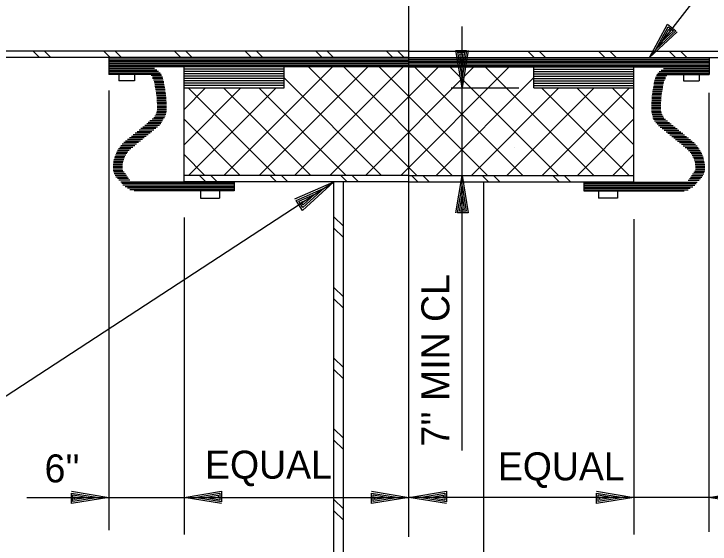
# Model space of a CAD drawing. Extents: x 22339.2 to 22413.4, y 22369.6 to 22418.8.
# Drawn here: x 22380.131 to 22384.774, y 22384.55 to 22388.086 of the extents above; entities that cross this region are included whole.
import ezdxf

# ---------------------------------------------------------------- set-up
doc = ezdxf.new("R2010")
doc.units = 0
for name, color, linetype in [('Level 1', 7, 'Continuous'), ('Level 10', 7, 'Continuous'), ('Level 2', 7, 'Continuous'), ('Level 4', 7, 'Continuous'), ('Level 8', 7, 'Continuous')]:
    doc.layers.add(name, color=color, linetype=linetype)

msp = doc.modelspace()

# ---------------------------------------------------------------- linework, layer by layer
at = {"layer": 'Level 1'}
for p, q in [((22382.7659, 22384.5979), (22382.7659, 22394.0328)), ((22383.1197, 22387.5922), (22383.1197, 22388.0015)), ((22381.2659, 22386.9672), (22381.2659, 22387.7328)), ((22381.9326, 22387.7172), (22381.2659, 22387.7172)), ((22383.5993, 22387.7172), (22384.2659, 22387.7172)), ((22384.2659, 22386.9672), (22384.2659, 22387.7328)), ((22380.8307, 22387.6831), (22380.8307, 22387.6401)), ((22380.9344, 22387.6831), (22380.9344, 22387.6401)), ((22381.9326, 22387.7015), (22381.2659, 22387.7015)), ((22381.9326, 22387.6859), (22381.2659, 22387.6859)), ((22381.9326, 22387.6703), (22381.2659, 22387.6703)), ((22383.5993, 22387.7015), (22384.2659, 22387.7015)), ((22383.5993, 22387.6859), (22384.2659, 22387.6859)), ((22383.5993, 22387.6703), (22384.2659, 22387.6703)), ((22384.5975, 22387.6831), (22384.5975, 22387.6401)), ((22384.7012, 22387.6831), (22384.7012, 22387.6401)), ((22380.9344, 22387.6401), (22380.8307, 22387.6401)), ((22381.9326, 22387.6547), (22381.2659, 22387.6547)), ((22381.9326, 22387.639), (22381.2659, 22387.639)), ((22381.9326, 22387.6234), (22381.2659, 22387.6234)), ((22383.5993, 22387.6547), (22384.2659, 22387.6547)), ((22383.5993, 22387.639), (22384.2659, 22387.639)), ((22383.5993, 22387.6234), (22384.2659, 22387.6234)), ((22384.5975, 22387.6401), (22384.7012, 22387.6401)), ((22380.7637, 22387.5759), (22380.7637, 22384.6433)), ((22381.9326, 22387.6078), (22381.2659, 22387.6078)), ((22383.0485, 22387.5922), (22383.4983, 22387.5922)), ((22383.1197, 22387.0088), (22383.1197, 22387.5922)), ((22383.1197, 22387.5713), (22383.1197, 22387.5713)), ((22383.5993, 22387.6078), (22384.2659, 22387.6078)), ((22384.7659, 22387.5605), (22384.7659, 22384.632)), ((22382.2659, 22387.2588), (22382.2659, 22387.2588)), ((22383.1197, 22387.252), (22383.1197, 22387.252)), ((22383.4403, 22387.2588), (22383.4403, 22387.2588)), ((22383.4701, 22387.1962), (22383.4701, 22387.1962)), ((22382.7659, 22387.0088), (22381.2659, 22387.0088)), ((22382.7659, 22386.9672), (22381.2659, 22386.9672)), ((22382.7659, 22387.0088), (22384.2659, 22387.0088)), ((22382.7659, 22386.9672), (22384.2659, 22386.9672)), ((22383.1197, 22385.1752), (22383.1197, 22387.0088)), ((22383.1197, 22386.9463), (22383.1197, 22386.9463)), ((22381.3747, 22386.9055), (22381.3747, 22386.8578)), ((22381.5022, 22386.9055), (22381.5022, 22386.8578)), ((22384.0297, 22386.9055), (22384.0297, 22386.8578)), ((22384.1572, 22386.9055), (22384.1572, 22386.8578)), ((22381.3747, 22386.8578), (22381.5022, 22386.8578)), ((22384.1572, 22386.8578), (22384.0297, 22386.8578)), ((22381.2659, 22386.7289), (22381.2659, 22384.6134)), ((22384.2659, 22386.7179), (22384.2659, 22384.6134)), ((22380.2182, 22384.8612), (22380.7637, 22384.8612)), ((22380.7637, 22384.8612), (22381.2659, 22384.8612)), ((22381.2659, 22384.8612), (22381.2659, 22384.8612)), ((22381.2659, 22384.8612), (22382.7659, 22384.8612)), ((22381.3353, 22384.8612), (22381.3353, 22384.8612)), ((22382.6966, 22384.8612), (22382.6966, 22384.8612)), ((22384.2659, 22384.8612), (22382.7659, 22384.8612)), ((22382.7659, 22384.8612), (22382.7659, 22384.8612)), ((22382.7659, 22384.8612), (22382.7659, 22384.8612)), ((22382.8353, 22384.8612), (22382.8353, 22384.8612)), ((22384.1966, 22384.8612), (22384.1966, 22384.8612)), ((22384.2659, 22384.8612), (22384.2659, 22384.8612)), ((22384.7659, 22384.8612), (22384.2659, 22384.8612)), ((22385.3645, 22384.8612), (22384.7659, 22384.8612))]:
    msp.add_line(p, q, dxfattribs=at)
at = {"layer": 'Level 10'}
for p, q in [((22379.2918, 22385.0258), (22382.2659, 22386.9672)), ((22382.2659, 22386.9672), (22382.2659, 22386.9672)), ((22382.2006, 22386.9245), (22382.2006, 22386.9245))]:
    msp.add_line(p, q, dxfattribs=at)
msp.add_lwpolyline([(22382.0056, 22386.8528), (22382.2659, 22386.9672), (22382.0565, 22386.7749), (22382.013, 22386.8415), (22382.2006, 22386.9245), (22382.0583, 22386.794), (22382.0304, 22386.8367), (22382.1378, 22386.8835), (22382.0602, 22386.8131), (22382.0487, 22386.8307), (22382.0725, 22386.8409)], dxfattribs=at)
at = {"layer": 'Level 2'}
for p, q in [((22385.4904, 22389.2365), (22384.3699, 22387.7953)), ((22382.7659, 22387.8369), (22376.0702, 22387.8369)), ((22382.7659, 22387.8369), (22389.4492, 22387.8369)), ((22382.7659, 22387.7953), (22376.1004, 22387.7953)), ((22380.7647, 22387.7953), (22380.7647, 22387.6831)), ((22382.7659, 22387.7849), (22380.7647, 22387.7849)), ((22382.7659, 22387.7744), (22380.7647, 22387.7744)), ((22382.7659, 22387.764), (22380.7647, 22387.764)), ((22382.7659, 22387.7953), (22389.4256, 22387.7953)), ((22382.7659, 22387.7849), (22384.7672, 22387.7849)), ((22382.7659, 22387.7744), (22384.7672, 22387.7744)), ((22382.7659, 22387.764), (22384.7672, 22387.764)), ((22384.7672, 22387.7953), (22384.7672, 22387.6831)), ((22382.7659, 22387.7536), (22380.7647, 22387.7536)), ((22382.7659, 22387.7432), (22380.7647, 22387.7432)), ((22382.7659, 22387.7328), (22380.7647, 22387.7328)), ((22381.2659, 22387.5922), (22381.2659, 22387.7328)), ((22381.9326, 22387.5922), (22381.9326, 22387.7328)), ((22382.7659, 22387.7536), (22384.7672, 22387.7536)), ((22382.7659, 22387.7432), (22384.7672, 22387.7432)), ((22382.7659, 22387.7328), (22384.7672, 22387.7328)), ((22383.5993, 22387.5922), (22383.5993, 22387.7328)), ((22384.2659, 22387.5922), (22384.2659, 22387.7328)), ((22381.1127, 22387.6831), (22380.7647, 22387.6831)), ((22384.4192, 22387.6831), (22384.7672, 22387.6831)), ((22381.2659, 22387.5922), (22381.9326, 22387.5922)), ((22383.5993, 22387.5922), (22384.2659, 22387.5922)), ((22381.6005, 22386.9672), (22381.6005, 22386.9055)), ((22382.2659, 22383.8568), (22382.2659, 22386.9672)), ((22382.3284, 22383.8568), (22382.3284, 22386.9672)), ((22383.2659, 22383.8568), (22383.2659, 22386.9672)), ((22383.9314, 22386.9672), (22383.9314, 22386.9055)), ((22381.6005, 22386.9055), (22380.932, 22386.9055)), ((22383.9314, 22386.9055), (22384.6009, 22386.9055))]:
    msp.add_line(p, q, dxfattribs=at)
for points in [[(22384.5555, 22387.9667), (22384.3699, 22387.7953), (22384.4903, 22388.0175), (22384.5461, 22387.9741), (22384.4124, 22387.85), (22384.4942, 22388.0009), (22384.53, 22387.9731), (22384.4533, 22387.9026), (22384.4982, 22387.9843), (22384.513, 22387.9728), (22384.4959, 22387.9574)], [(22383.161, 22387.8415), (22383.1197, 22387.5922), (22383.0784, 22387.8415), (22383.149, 22387.8415), (22383.1197, 22387.6615), (22383.0917, 22387.8308), (22383.137, 22387.8308), (22383.1197, 22387.7282), (22383.105, 22387.8202), (22383.1237, 22387.8202), (22383.1197, 22387.7975)], [(22381.0479, 22387.7328), (22380.7647, 22387.7328)], [(22381.0684, 22387.7224), (22380.7659, 22387.7224)], [(22381.0838, 22387.7119), (22380.7659, 22387.7119)], [(22384.4481, 22387.7119), (22384.7659, 22387.7119)], [(22384.4635, 22387.7224), (22384.7659, 22387.7224)], [(22384.484, 22387.7328), (22384.7672, 22387.7328)], [(22381.0962, 22387.7015), (22380.7659, 22387.7015)], [(22381.1064, 22387.6911), (22380.7659, 22387.6911)], [(22381.1159, 22387.6755), (22381.0462, 22387.6755)], [(22381.1212, 22387.6651), (22381.0543, 22387.6651)], [(22384.4107, 22387.6651), (22384.4776, 22387.6651)], [(22384.4159, 22387.6755), (22384.4857, 22387.6755)], [(22384.4255, 22387.6911), (22384.7659, 22387.6911)], [(22384.4357, 22387.7015), (22384.7659, 22387.7015)], [(22381.1246, 22387.6547), (22381.0559, 22387.6547)], [(22381.1274, 22387.6442), (22381.0622, 22387.6442)], [(22381.1298, 22387.6338), (22381.0654, 22387.6338)], [(22381.1318, 22387.6234), (22381.068, 22387.6234)], [(22384.4001, 22387.6234), (22384.4639, 22387.6234)], [(22384.4021, 22387.6338), (22384.4665, 22387.6338)], [(22384.4045, 22387.6442), (22384.4697, 22387.6442)], [(22384.4073, 22387.6547), (22384.476, 22387.6547)], [(22381.1336, 22387.613), (22381.0702, 22387.613)], [(22381.1354, 22387.6026), (22381.0719, 22387.6026)], [(22381.1371, 22387.5922), (22381.0737, 22387.5922)], [(22381.139, 22387.5817), (22381.0755, 22387.5817)], [(22381.1408, 22387.5713), (22381.0773, 22387.5713)], [(22384.3911, 22387.5713), (22384.4546, 22387.5713)], [(22384.3929, 22387.5817), (22384.4564, 22387.5817)], [(22384.3948, 22387.5922), (22384.4582, 22387.5922)], [(22384.3965, 22387.6026), (22384.46, 22387.6026)], [(22384.3983, 22387.613), (22384.4617, 22387.613)], [(22381.1425, 22387.5609), (22381.0791, 22387.5609)], [(22381.1441, 22387.5505), (22381.0808, 22387.5505)], [(22381.1453, 22387.5401), (22381.0823, 22387.5401)], [(22381.146, 22387.5297), (22381.0833, 22387.5297)], [(22384.3859, 22387.5297), (22384.4486, 22387.5297)], [(22384.3866, 22387.5401), (22384.4496, 22387.5401)], [(22384.3878, 22387.5505), (22384.4511, 22387.5505)], [(22384.3894, 22387.5609), (22384.4527, 22387.5609)], [(22381.1465, 22387.5192), (22381.084, 22387.5192)], [(22381.1471, 22387.5088), (22381.0845, 22387.5088)], [(22381.1477, 22387.4984), (22381.0851, 22387.4984)], [(22381.1485, 22387.4776), (22381.0854, 22387.4776)], [(22381.1483, 22387.488), (22381.0857, 22387.488)], [(22384.3834, 22387.4776), (22384.4465, 22387.4776)], [(22384.3836, 22387.488), (22384.4462, 22387.488)], [(22384.3842, 22387.4984), (22384.4468, 22387.4984)], [(22384.3848, 22387.5088), (22384.4474, 22387.5088)], [(22384.3853, 22387.5192), (22384.4479, 22387.5192)], [(22381.1477, 22387.4359), (22381.0842, 22387.4359)], [(22381.1489, 22387.4463), (22381.0861, 22387.4463)], [(22381.1493, 22387.4672), (22381.0867, 22387.4672)], [(22381.1494, 22387.4567), (22381.0869, 22387.4567)], [(22384.3825, 22387.4567), (22384.445, 22387.4567)], [(22384.3826, 22387.4672), (22384.4452, 22387.4672)], [(22384.383, 22387.4463), (22384.4458, 22387.4463)], [(22384.3841, 22387.4359), (22384.4477, 22387.4359)], [(22381.1275, 22387.3838), (22381.0522, 22387.3838)], [(22381.1361, 22387.3942), (22381.0639, 22387.3942)], [(22381.1401, 22387.4047), (22381.0713, 22387.4047)], [(22381.1434, 22387.4151), (22381.077, 22387.4151)], [(22381.1459, 22387.4255), (22381.0812, 22387.4255)], [(22384.386, 22387.4255), (22384.4507, 22387.4255)], [(22384.3885, 22387.4151), (22384.4549, 22387.4151)], [(22384.3918, 22387.4047), (22384.4606, 22387.4047)], [(22384.3918, 22387.3942), (22384.4666, 22387.3942)], [(22384.3968, 22387.3838), (22384.478, 22387.3838)], [(22381.1011, 22387.3422), (22381.0037, 22387.3422)], [(22381.1105, 22387.3526), (22381.0164, 22387.3526)], [(22381.1147, 22387.363), (22381.0253, 22387.363)], [(22381.1218, 22387.3734), (22381.0366, 22387.3734)], [(22384.4032, 22387.3734), (22384.4894, 22387.3734)], [(22384.4133, 22387.363), (22384.5027, 22387.363)], [(22384.4213, 22387.3526), (22384.5155, 22387.3526)], [(22384.4308, 22387.3422), (22384.5282, 22387.3422)], [(22381.0387, 22387.2901), (22380.9398, 22387.2901)], [(22381.0515, 22387.3005), (22380.9526, 22387.3005)], [(22381.0642, 22387.3109), (22380.9654, 22387.3109)], [(22381.077, 22387.3213), (22380.9781, 22387.3213)], [(22381.0897, 22387.3317), (22380.9909, 22387.3317)], [(22384.4422, 22387.3317), (22384.541, 22387.3317)], [(22384.4549, 22387.3213), (22384.5538, 22387.3213)], [(22384.4677, 22387.3109), (22384.5665, 22387.3109)], [(22384.4804, 22387.3005), (22384.5793, 22387.3005)], [(22384.4932, 22387.2901), (22384.5921, 22387.2901)], [(22380.9876, 22387.2484), (22380.8888, 22387.2484)], [(22381.0004, 22387.2588), (22380.9015, 22387.2588)], [(22381.0132, 22387.2692), (22380.9143, 22387.2692)], [(22381.0259, 22387.2797), (22380.9271, 22387.2797)], [(22384.506, 22387.2797), (22384.6048, 22387.2797)], [(22384.5187, 22387.2692), (22384.6176, 22387.2692)], [(22384.5315, 22387.2588), (22384.6304, 22387.2588)], [(22384.5443, 22387.2484), (22384.6431, 22387.2484)], [(22380.9365, 22387.2067), (22380.8447, 22387.2067)], [(22380.9493, 22387.2172), (22380.8538, 22387.2172)], [(22380.9621, 22387.2276), (22380.8642, 22387.2276)], [(22380.9749, 22387.238), (22380.876, 22387.238)], [(22384.557, 22387.238), (22384.6559, 22387.238)], [(22384.5698, 22387.2276), (22384.6677, 22387.2276)], [(22384.5826, 22387.2172), (22384.6781, 22387.2172)], [(22384.5953, 22387.2067), (22384.6872, 22387.2067)], [(22380.8836, 22387.1547), (22380.8123, 22387.1547)], [(22380.8913, 22387.1651), (22380.8173, 22387.1651)], [(22380.9004, 22387.1755), (22380.8229, 22387.1755)], [(22380.9112, 22387.1859), (22380.8293, 22387.1859)], [(22380.9238, 22387.1963), (22380.8365, 22387.1963)], [(22384.6081, 22387.1963), (22384.6953, 22387.1963)], [(22384.6207, 22387.1859), (22384.7026, 22387.1859)], [(22384.6315, 22387.1755), (22384.709, 22387.1755)], [(22384.6406, 22387.1651), (22384.7146, 22387.1651)], [(22384.6483, 22387.1547), (22384.7196, 22387.1547)], [(22380.8631, 22387.113), (22380.7982, 22387.113)], [(22380.8669, 22387.1234), (22380.8009, 22387.1234)], [(22380.8715, 22387.1338), (22380.8041, 22387.1338)], [(22380.8771, 22387.1442), (22380.8079, 22387.1442)], [(22384.6548, 22387.1442), (22384.724, 22387.1442)], [(22384.6604, 22387.1338), (22384.7278, 22387.1338)], [(22384.665, 22387.1234), (22384.731, 22387.1234)], [(22384.6688, 22387.113), (22384.7337, 22387.113)], [(22380.8547, 22387.0609), (22380.7922, 22387.0609)], [(22380.855, 22387.0713), (22380.7924, 22387.0713)], [(22380.856, 22387.0817), (22380.7931, 22387.0817)], [(22380.8577, 22387.0922), (22380.7943, 22387.0922)], [(22380.86, 22387.1026), (22380.796, 22387.1026)], [(22384.6719, 22387.1026), (22384.7359, 22387.1026)], [(22384.6742, 22387.0922), (22384.7376, 22387.0922)], [(22384.6759, 22387.0817), (22384.7387, 22387.0817)], [(22384.6769, 22387.0713), (22384.7395, 22387.0713)], [(22384.6772, 22387.0609), (22384.7397, 22387.0609)], [(22380.855, 22387.0505), (22380.7924, 22387.0505)], [(22380.8582, 22387.0401), (22380.7931, 22387.0401)], [(22380.8653, 22387.0297), (22380.797, 22387.0297)], [(22380.875, 22387.0192), (22380.7995, 22387.0192)], [(22384.6569, 22387.0192), (22384.7324, 22387.0192)], [(22384.6666, 22387.0297), (22384.7349, 22387.0297)], [(22384.6737, 22387.0401), (22384.7388, 22387.0401)], [(22384.6769, 22387.0505), (22384.7395, 22387.0505)], [(22380.8821, 22387.0088), (22380.8053, 22387.0088)], [(22380.8885, 22386.9984), (22380.8118, 22386.9984)], [(22380.8944, 22386.988), (22380.8208, 22386.988)], [(22380.9034, 22386.9776), (22380.8311, 22386.9776)], [(22381.5993, 22386.965), (22380.8434, 22386.965)], [(22383.0784, 22386.7595), (22383.1197, 22387.0088), (22383.161, 22386.7595), (22383.0904, 22386.7595), (22383.1197, 22386.9395), (22383.1477, 22386.7702), (22383.1024, 22386.7702), (22383.1197, 22386.8728), (22383.1344, 22386.7808), (22383.1157, 22386.7808), (22383.1197, 22386.8035)], [(22383.9326, 22386.965), (22384.6885, 22386.965)], [(22384.6285, 22386.9776), (22384.7007, 22386.9776)], [(22384.6375, 22386.988), (22384.7111, 22386.988)], [(22384.6433, 22386.9984), (22384.7201, 22386.9984)], [(22384.6498, 22387.0088), (22384.7265, 22387.0088)], [(22381.5993, 22386.9545), (22380.8499, 22386.9545)], [(22381.5993, 22386.9441), (22380.8584, 22386.9441)], [(22381.5993, 22386.9337), (22380.8736, 22386.9337)], [(22381.5993, 22386.9233), (22380.8895, 22386.9233)], [(22383.9326, 22386.9545), (22384.682, 22386.9545)], [(22383.9326, 22386.9441), (22384.6735, 22386.9441)], [(22383.9326, 22386.9337), (22384.6582, 22386.9337)], [(22383.9326, 22386.9233), (22384.6424, 22386.9233)], [(22381.5993, 22386.9129), (22380.9047, 22386.9129)], [(22383.9326, 22386.9129), (22384.6272, 22386.9129)], [(22380.5144, 22384.9025), (22380.7637, 22384.8612), (22380.5144, 22384.8199), (22380.5144, 22384.8905), (22380.6944, 22384.8612), (22380.525, 22384.8332), (22380.525, 22384.8785), (22380.6277, 22384.8612), (22380.5357, 22384.8465), (22380.5357, 22384.8652), (22380.5584, 22384.8612)], [(22381.5153, 22384.8199), (22381.2659, 22384.8612), (22381.5153, 22384.9025), (22381.5153, 22384.8319), (22381.3353, 22384.8612), (22381.5046, 22384.8892), (22381.5046, 22384.8439), (22381.4019, 22384.8612), (22381.4939, 22384.8759), (22381.4939, 22384.8572), (22381.4713, 22384.8612)], [(22382.5166, 22384.9025), (22382.7659, 22384.8612), (22382.5166, 22384.8199), (22382.5166, 22384.8905), (22382.6966, 22384.8612), (22382.5273, 22384.8332), (22382.5273, 22384.8785), (22382.6299, 22384.8612), (22382.5379, 22384.8465), (22382.5379, 22384.8652), (22382.5606, 22384.8612)], [(22383.0153, 22384.8199), (22382.7659, 22384.8612), (22383.0153, 22384.9025), (22383.0153, 22384.8319), (22382.8353, 22384.8612), (22383.0046, 22384.8892), (22383.0046, 22384.8439), (22382.9019, 22384.8612), (22382.9939, 22384.8759), (22382.9939, 22384.8572), (22382.9713, 22384.8612)], [(22384.0166, 22384.9025), (22384.2659, 22384.8612), (22384.0166, 22384.8199), (22384.0166, 22384.8905), (22384.1966, 22384.8612), (22384.0273, 22384.8332), (22384.0273, 22384.8785), (22384.1299, 22384.8612), (22384.0379, 22384.8465), (22384.0379, 22384.8652), (22384.0606, 22384.8612)], [(22385.0153, 22384.8199), (22384.7659, 22384.8612), (22385.0153, 22384.9025), (22385.0153, 22384.8319), (22384.8353, 22384.8612), (22385.0046, 22384.8892), (22385.0046, 22384.8439), (22384.9019, 22384.8612), (22384.9939, 22384.8759), (22384.9939, 22384.8572), (22384.9713, 22384.8612)]]:
    msp.add_lwpolyline(points, dxfattribs=at)
at = {"layer": 'Level 8'}
for p, q in [((22384.4124, 22387.85), (22384.4124, 22387.85)), ((22384.3699, 22387.7953), (22384.3699, 22387.7953)), ((22383.1197, 22387.6615), (22383.1197, 22387.6615)), ((22383.1197, 22387.5922), (22383.1197, 22387.5922)), ((22383.1197, 22387.0088), (22383.1197, 22387.0088)), ((22383.1197, 22386.9395), (22383.1197, 22386.9395)), ((22380.6944, 22384.8612), (22380.6944, 22384.8612)), ((22380.7637, 22384.8612), (22380.7637, 22384.8612)), ((22381.2659, 22384.8612), (22381.2659, 22384.8612)), ((22381.3353, 22384.8612), (22381.3353, 22384.8612)), ((22382.6966, 22384.8612), (22382.6966, 22384.8612)), ((22382.7659, 22384.8612), (22382.7659, 22384.8612)), ((22382.7659, 22384.8612), (22382.7659, 22384.8612)), ((22382.8353, 22384.8612), (22382.8353, 22384.8612)), ((22384.1966, 22384.8612), (22384.1966, 22384.8612)), ((22384.2659, 22384.8612), (22384.2659, 22384.8612)), ((22384.7659, 22384.8612), (22384.7659, 22384.8612))]:
    msp.add_line(p, q, dxfattribs=at)
for points in [[(22380.3011, 22387.7953), (22380.2595, 22387.8369)], [(22380.3766, 22387.7953), (22380.3349, 22387.8369)], [(22380.7725, 22387.7953), (22380.7309, 22387.8369)], [(22380.848, 22387.7953), (22380.8063, 22387.8369)], [(22381.244, 22387.7953), (22381.2023, 22387.8369)], [(22381.3194, 22387.7953), (22381.2777, 22387.8369)], [(22381.7154, 22387.7953), (22381.6737, 22387.8369)], [(22381.7908, 22387.7953), (22381.7491, 22387.8369)], [(22382.1868, 22387.7953), (22382.1451, 22387.8369)], [(22382.2622, 22387.7953), (22382.2205, 22387.8369)], [(22382.6582, 22387.7953), (22382.6165, 22387.8369)], [(22382.7336, 22387.7953), (22382.6919, 22387.8369)], [(22383.601, 22387.7953), (22383.5593, 22387.8369)], [(22383.6764, 22387.7953), (22383.6347, 22387.8369)], [(22384.0724, 22387.7953), (22384.0307, 22387.8369)], [(22384.1478, 22387.7953), (22384.1061, 22387.8369)], [(22384.5438, 22387.7953), (22384.5021, 22387.8369)], [(22384.6192, 22387.7953), (22384.5775, 22387.8369)], [(22381.5321, 22387.0088), (22382.2561, 22387.7328)], [(22381.7678, 22387.0088), (22382.4918, 22387.7328)], [(22382.0035, 22387.0088), (22382.7275, 22387.7328)], [(22382.8194, 22387.0088), (22382.0954, 22387.7328)], [(22382.2392, 22387.0088), (22382.9632, 22387.7328)], [(22383.0551, 22387.0088), (22382.3311, 22387.7328)], [(22382.4749, 22387.0088), (22383.1989, 22387.7328)], [(22383.2908, 22387.0088), (22382.5668, 22387.7328)], [(22382.7106, 22387.0088), (22383.4346, 22387.7328)], [(22383.5265, 22387.0088), (22382.8025, 22387.7328)], [(22383.7622, 22387.0088), (22383.0382, 22387.7328)], [(22383.9979, 22387.0088), (22383.274, 22387.7328)], [(22382.9463, 22387.0088), (22383.5993, 22387.6618)], [(22382.5837, 22387.0088), (22381.9326, 22387.6599)], [(22381.2659, 22387.2141), (22381.644, 22387.5922)], [(22381.2659, 22387.4497), (22381.4084, 22387.5922)], [(22381.8766, 22387.0088), (22381.2932, 22387.5922)], [(22381.2964, 22387.0088), (22381.8798, 22387.5922)], [(22382.1123, 22387.0088), (22381.529, 22387.5922)], [(22382.348, 22387.0088), (22381.7647, 22387.5922)], [(22383.182, 22387.0088), (22383.7654, 22387.5922)], [(22383.4177, 22387.0088), (22384.0011, 22387.5922)], [(22384.2336, 22387.0088), (22383.6503, 22387.5922)], [(22383.6534, 22387.0088), (22384.2368, 22387.5922)], [(22384.2659, 22387.2122), (22383.886, 22387.5922)], [(22384.2659, 22387.4479), (22384.1217, 22387.5922)], [(22381.6409, 22387.0088), (22381.2659, 22387.3838)], [(22383.8892, 22387.0088), (22384.2659, 22387.3856)], [(22381.4052, 22387.0088), (22381.2659, 22387.1481)], [(22384.1248, 22387.0088), (22384.2659, 22387.1499)], [(22381.4103, 22386.9672), (22381.3686, 22387.0088)], [(22381.4857, 22386.9672), (22381.4441, 22387.0088)], [(22381.8817, 22386.9672), (22381.84, 22387.0088)], [(22381.9571, 22386.9672), (22381.9155, 22387.0088)], [(22382.3531, 22386.9672), (22382.3114, 22387.0088)], [(22382.4285, 22386.9672), (22382.3869, 22387.0088)], [(22382.8245, 22386.9672), (22382.7828, 22387.0088)], [(22382.8999, 22386.9672), (22382.8583, 22387.0088)], [(22383.2959, 22386.9672), (22383.2542, 22387.0088)], [(22383.3714, 22386.9672), (22383.3297, 22387.0088)], [(22383.7673, 22386.9672), (22383.7257, 22387.0088)], [(22383.8428, 22386.9672), (22383.8011, 22387.0088)], [(22382.3284, 22386.671), (22382.2659, 22386.7335)], [(22382.3284, 22386.5955), (22382.2659, 22386.658)], [(22382.3284, 22386.1996), (22382.2659, 22386.2621)], [(22382.3284, 22386.1241), (22382.2659, 22386.1866)], [(22382.3284, 22385.7282), (22382.2659, 22385.7907)], [(22382.3284, 22385.6527), (22382.2659, 22385.7152)], [(22382.3284, 22385.2568), (22382.2659, 22385.3193)], [(22382.3284, 22385.1813), (22382.2659, 22385.2438)], [(22382.3284, 22384.7854), (22382.2659, 22384.8479)], [(22382.3284, 22384.7099), (22382.2659, 22384.7724)]]:
    msp.add_lwpolyline(points, dxfattribs=at)

# ---------------------------------------------------------------- texts
at = {"layer": 'Level 4'}
msp.add_text("7'' MIN CL ", height=0.186667, rotation=90, dxfattribs=at).set_placement((22383.0354, 22385.2012))
for s, p in [('EQUAL', (22381.4057, 22384.9863)), ('EQUAL', (22383.3588, 22384.9751)), ("6''", (22380.3354, 22384.9615))]:
    msp.add_text(s, height=0.18667, dxfattribs=at).set_placement(p)

doc.saveas('drawing.dxf')
